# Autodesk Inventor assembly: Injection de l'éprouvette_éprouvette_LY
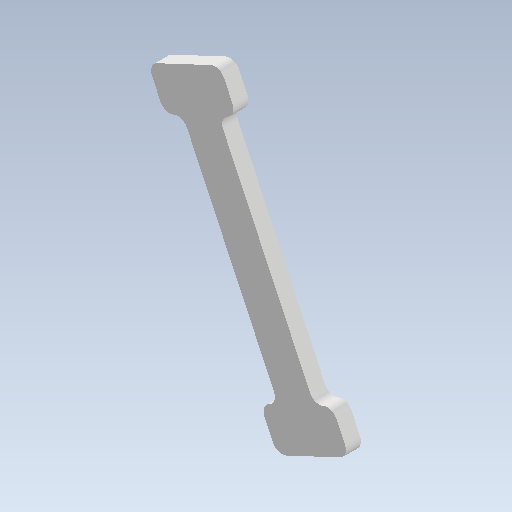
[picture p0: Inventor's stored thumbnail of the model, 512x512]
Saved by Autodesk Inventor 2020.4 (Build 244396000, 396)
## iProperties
Created: 2021-10
Part Number: Injection de l'éprouvette_éprouvette_LY
Document SubType Name: Assembly
Designer: mel
Author: mel
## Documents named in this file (2)
- D:\travail\année 2020-2021\itec\prépa injection plastique eduscol\dossier de travail\Ensemble des pièces de l'activité\Conception de moule1\Injection de l'éprouvette_éprouvette_LY.iam
- D:\travail\année 2020-2021\itec\prépa injection plastique eduscol\dossier de travail\Ensemble des pièces de l'activité\Conception de moule1\Injection de l'éprouvette_éprouvette_PZ.iam
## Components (1 placed, 1 different names)
1. Injection de l'éprouvette_éprouvette_PZ:1 [sub-assembly] — Affleurement:1, Affleurement:2, Affleurement:3
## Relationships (3: Flush 3)
- Affleurement:1 [Flush]: Injection de l'éprouvette_éprouvette_PZ:1
- Affleurement:2 [Flush]: Injection de l'éprouvette_éprouvette_PZ:1
- Affleurement:3 [Flush]: Injection de l'éprouvette_éprouvette_PZ:1
